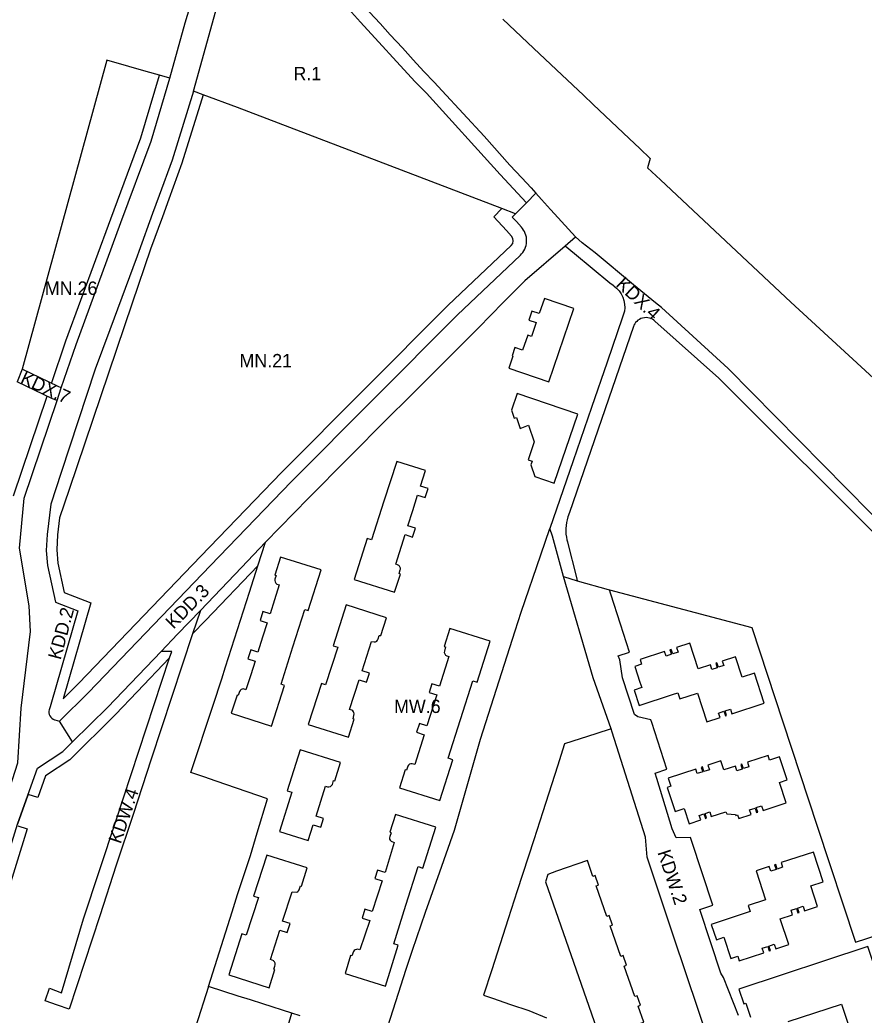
# Model space of a CAD drawing. Extents: x 7416797 to 7419013, y 5549660 to 5551534.
# Drawn here: x 7417362.3 to 7417678.6, y 5550624.8 to 5550997.5 of the extents above; entities that cross this region are included whole.
import ezdxf

# ---------------------------------------------------------------- set-up
doc = ezdxf.new("R2010")
doc.units = 0
for name, color, linetype in [('LIN_Linia Zabudowy Nieprzekraczalna', 7, 'Continuous'), ('LIN_Linia Zabudowy Obowiązujaca', 7, 'Continuous'), ('LIN_linie_rozgraniczajace', 7, 'Continuous'), ('TXT_Oznaczenia_przeznaczen', 7, 'Continuous')]:
    doc.layers.add(name, color=color, linetype=linetype)

msp = doc.modelspace()

# ---------------------------------------------------------------- linework, layer by layer
at = {"layer": 'LIN_Linia Zabudowy Nieprzekraczalna'}
msp.add_line((7417543.12, 5550920.3), (7417544.66, 5550918.61), dxfattribs=at)
for points in [[(7417374.19, 5550861.35), (7417379.59, 5550877.27), (7417396.44, 5550923.04), (7417407.68, 5550953.34), (7417414.63, 5550976.83)], [(7417431.02, 5550969.42), (7417423.05, 5550943.81), (7417418.15, 5550930.44), (7417415.7, 5550923.73), (7417411.27, 5550911.64)], [(7417546.54, 5550916.54), (7417544.66, 5550918.61), (7417539.91, 5550923.81), (7417542.9, 5550926.83)], [(7417377.21, 5550811.01), (7417376.47, 5550804.65), (7417376.12, 5550799.09), (7417376.56, 5550794.09), (7417378.94, 5550783.04), (7417388.87, 5550779.22), (7417378.53, 5550743.27), (7417384.4, 5550749.09), (7417430.11, 5550796.7), (7417460.4, 5550828.04), (7417522.84, 5550890.7), (7417546.41, 5550913.04)], [(7417411.27, 5550911.64), (7417404.39, 5550891.44), (7417380.8, 5550821.69), (7417377.21, 5550811.01)], [(7417359.92, 5550819.22), (7417372.58, 5550856.58)], [(7417451.53, 5550793.03), (7417431.87, 5550772.61), (7417427.03, 5550767.55)], [(7417418.42, 5550758.55), (7417406.27, 5550745.84), (7417398.18, 5550737.38), (7417380.98, 5550720.38), (7417371.85, 5550714.38), (7417369.03, 5550706.25), (7417365.43, 5550707.39), (7417365.35, 5550707.16), (7417361.36, 5550696.33)], [(7417361.58, 5550695.63), (7417365.01, 5550694.6), (7417356.26, 5550666.29)], [(7417399.46, 5550459.54), (7417410.81, 5550455.77), (7417421, 5550486.78), (7417446.8, 5550568.03), (7417455.32, 5550595.79), (7417464.2, 5550625.52)]]:
    msp.add_lwpolyline(points, dxfattribs=at)
msp.add_arc((7417544.69, 5550914.85), 2.5, 313.4663, 42.3592, dxfattribs=at)
at = {"layer": 'LIN_Linia Zabudowy Obowiązujaca'}
for p, q in [((7417509.59, 5550813.78), (7417511.33, 5550819.54)), ((7417464.61, 5550762.7), (7417469.04, 5550776.73)), ((7417460.17, 5550748.69), (7417464.61, 5550762.7)), ((7417476.79, 5550710.49), (7417477.57, 5550710.25))]:
    msp.add_line(p, q, dxfattribs=at)
for points in [[(7417569.85, 5550889.48), (7417558.85, 5550893.19), (7417556.92, 5550887.5), (7417554.13, 5550888.45), (7417553, 5550885.09), (7417555.79, 5550884.16), (7417554.05, 5550879.01), (7417552.61, 5550879.49), (7417550.68, 5550873.83), (7417547.8, 5550874.79), (7417546.72, 5550871.71), (7417547.03, 5550871.61), (7417545.49, 5550867.1), (7417560.47, 5550861.95)], [(7417562.53, 5550824.03), (7417571.34, 5550849.82), (7417548.61, 5550857.59), (7417546.46, 5550851.36), (7417547.52, 5550848.32), (7417548.34, 5550848.61), (7417549.79, 5550844.55), (7417552.91, 5550845.78), (7417555.05, 5550839.52), (7417552.78, 5550832.8), (7417554.2, 5550832.32), (7417553.75, 5550830.86), (7417555.3, 5550826.52)], [(7417603.89, 5550760.97), (7417594.7, 5550757.96), (7417595.27, 5550756.24), (7417592.69, 5550755.39), (7417594.64, 5550749.47), (7417595.3, 5550747.48), (7417592.46, 5550746.53), (7417594.35, 5550740.76), (7417606.87, 5550744.88), (7417608.88, 5550745.54), (7417609.63, 5550743.26), (7417616.19, 5550745.42), (7417619.75, 5550734.6), (7417624.64, 5550736.21), (7417624.08, 5550737.92), (7417626.08, 5550738.58), (7417626.65, 5550736.87), (7417627.11, 5550737.02), (7417626.55, 5550738.73), (7417628.55, 5550739.39), (7417629.12, 5550737.68), (7417641.19, 5550741.64), (7417637.53, 5550752.83), (7417632.97, 5550751.34), (7417630.43, 5550759.02), (7417625.51, 5550757.38), (7417626.07, 5550755.69), (7417624.06, 5550755.05), (7417623.5, 5550756.74), (7417623.04, 5550756.58), (7417623.6, 5550754.91), (7417621.59, 5550754.24), (7417621.02, 5550755.93), (7417616.47, 5550754.44), (7417613.29, 5550764.07), (7417608.39, 5550762.45), (7417608.95, 5550760.73), (7417606.92, 5550760.07), (7417606.35, 5550761.79), (7417605.9, 5550761.63), (7417606.46, 5550759.93), (7417604.46, 5550759.27)], [(7417605.27, 5550713.53), (7417606.27, 5550710.49), (7417604.84, 5550710.03), (7417607.81, 5550701.05), (7417611.22, 5550702.15), (7417613.08, 5550696.45), (7417617.44, 5550697.88), (7417616.89, 5550699.6), (7417618.6, 5550700.16), (7417619.16, 5550698.45), (7417619.63, 5550698.6), (7417619.07, 5550700.32), (7417620.78, 5550700.88), (7417621.35, 5550699.17), (7417626.87, 5550700.97), (7417627.14, 5550700.16), (7417630.47, 5550699.89), (7417630.58, 5550699.59), (7417631.23, 5550699.86), (7417631.69, 5550698.47), (7417636.31, 5550699.98), (7417635.75, 5550701.7), (7417637.78, 5550702.36), (7417638.33, 5550700.65), (7417638.78, 5550700.8), (7417638.22, 5550702.51), (7417640.25, 5550703.17), (7417640.81, 5550701.46), (7417649.45, 5550704.29), (7417646.94, 5550711.97), (7417649.77, 5550712.9), (7417646.94, 5550721.53), (7417643.22, 5550720.32), (7417642.66, 5550722.03), (7417634.9, 5550719.48), (7417635.46, 5550717.77), (7417633.43, 5550717.1), (7417632.87, 5550718.81), (7417632.43, 5550718.67), (7417632.99, 5550716.96), (7417630.96, 5550716.29), (7417630.4, 5550718.01), (7417626.12, 5550716.62), (7417624.99, 5550720.02), (7417620.08, 5550718.41), (7417620.65, 5550716.69), (7417618.61, 5550716.03), (7417618.06, 5550717.74), (7417617.61, 5550717.59), (7417618.17, 5550715.89), (7417616.13, 5550715.23), (7417615.6, 5550716.93)], [(7417563.44, 5550678.69), (7417560.16, 5550677.49), (7417559.27, 5550674.67), (7417578.38, 5550619.91), (7417581.25, 5550617.11), (7417584.57, 5550618.16), (7417596.07, 5550622.21), (7417593.98, 5550628.2), (7417594.83, 5550628.5), (7417593.6, 5550632.03), (7417592.75, 5550631.73), (7417588.77, 5550643.17), (7417589.64, 5550643.47), (7417588.37, 5550647.07), (7417587.51, 5550646.77), (7417583.53, 5550658.19), (7417584.37, 5550658.48), (7417583.15, 5550662.08), (7417582.28, 5550661.78), (7417578.3, 5550673.18), (7417579.15, 5550673.48), (7417577.91, 5550677.07), (7417577.05, 5550676.77), (7417574.97, 5550682.74)], [(7417638.19, 5550678.84), (7417641.7, 5550667.99), (7417635.14, 5550665.84), (7417635.89, 5550663.57), (7417621.36, 5550658.78), (7417623.28, 5550653.01), (7417626.13, 5550653.96), (7417628.72, 5550646.05), (7417631.29, 5550646.91), (7417631.85, 5550645.17), (7417641.02, 5550648.14), (7417640.47, 5550649.86), (7417642.51, 5550650.53), (7417643.07, 5550648.82), (7417643.5, 5550648.95), (7417642.92, 5550650.66), (7417644.96, 5550651.33), (7417645.53, 5550649.63), (7417650.43, 5550651.23), (7417647.19, 5550660.87), (7417651.82, 5550662.37), (7417651.26, 5550664.07), (7417653.28, 5550664.74), (7417653.84, 5550663.05), (7417654.28, 5550663.19), (7417653.71, 5550664.88), (7417655.75, 5550665.56), (7417656.31, 5550663.86), (7417661.23, 5550665.47), (7417658.73, 5550673.17), (7417663.29, 5550674.68), (7417659.64, 5550685.83), (7417647.56, 5550681.92), (7417648.12, 5550680.19), (7417646.09, 5550679.52), (7417645.54, 5550681.23), (7417645.09, 5550681.1), (7417645.67, 5550679.38), (7417643.63, 5550678.71), (7417643.07, 5550680.42)]]:
    msp.add_lwpolyline(points, close=True, dxfattribs=at)
for points in [[(7417511.33, 5550819.54), (7417514.17, 5550818.67), (7417515.24, 5550821.99), (7417512.43, 5550822.91), (7417514.25, 5550828.77), (7417503.51, 5550832.15), (7417498.72, 5550817.23)], [(7417498.72, 5550817.23), (7417494.12, 5550802.75), (7417492.43, 5550803.29), (7417487.55, 5550787.92)], [(7417503.76, 5550793.42), (7417503.13, 5550793.65), (7417506.65, 5550804.75), (7417509.47, 5550803.81), (7417510.51, 5550807.15), (7417507.71, 5550808.03), (7417509.59, 5550813.78)], [(7417459.97, 5550796.34), (7417457.85, 5550789.61), (7417458.32, 5550789.46), (7417457.87, 5550788.03)], [(7417469.04, 5550776.73), (7417470.31, 5550776.33), (7417475.14, 5550791.56), (7417459.97, 5550796.34)], [(7417487.55, 5550787.92), (7417502.7, 5550783.18), (7417504.97, 5550789.96), (7417504.42, 5550790.16), (7417504.86, 5550791.52)], [(7417458.53, 5550786.22), (7417459.48, 5550785.92), (7417457.71, 5550780.31)], [(7417457.71, 5550780.31), (7417456.04, 5550775.08), (7417453.36, 5550775.94), (7417452.29, 5550772.59), (7417454.98, 5550771.73), (7417453.25, 5550766.29)], [(7417496.61, 5550765.71), (7417496.93, 5550767.01), (7417497.56, 5550766.91), (7417499.66, 5550773.64), (7417484.59, 5550778.48), (7417479.65, 5550763.1), (7417481.4, 5550762.54), (7417476.88, 5550748.48), (7417475.28, 5550748.99), (7417470.35, 5550733.64)], [(7417507.62, 5550718), (7417507.12, 5550716.53), (7417506.67, 5550716.71), (7417504.54, 5550709.95), (7417519.69, 5550705.17), (7417524.52, 5550720.44), (7417522.8, 5550721), (7417531.99, 5550750.03), (7417533.7, 5550749.51), (7417538.57, 5550764.8), (7417523.41, 5550769.61)], [(7417523.41, 5550769.61), (7417521.29, 5550762.83), (7417521.78, 5550762.73), (7417521.39, 5550761.16)], [(7417453.25, 5550766.29), (7417451.5, 5550760.79), (7417448.84, 5550761.63), (7417447.77, 5550758.27), (7417450.43, 5550757.42), (7417448.81, 5550752.29)], [(7417486.7, 5550739.02), (7417485.84, 5550739.31), (7417489.41, 5550750.34), (7417492.17, 5550749.44), (7417493.28, 5550752.88), (7417490.53, 5550753.77), (7417494.07, 5550764.72), (7417495.02, 5550764.59)], [(7417522.32, 5550759.36), (7417523.04, 5550759.11), (7417519.53, 5550748.01), (7417516.69, 5550748.91), (7417515.68, 5550745.58), (7417518.48, 5550744.69), (7417514.82, 5550733.15), (7417512.01, 5550734.04), (7417510.95, 5550730.71), (7417513.76, 5550729.82), (7417510.25, 5550718.72), (7417509.36, 5550718.95)], [(7417448.81, 5550752.29), (7417447.01, 5550746.65), (7417446.06, 5550746.96)], [(7417444.66, 5550746.02), (7417444.15, 5550744.46), (7417443.68, 5550744.61), (7417441.48, 5550737.85), (7417456.59, 5550733.06), (7417461.42, 5550748.29), (7417460.17, 5550748.69)], [(7417470.35, 5550733.64), (7417485.43, 5550728.88), (7417487.56, 5550735.63), (7417487.13, 5550735.77), (7417487.62, 5550737.68)], [(7417479.4, 5550711.2), (7417479.85, 5550712.66), (7417480.32, 5550712.52), (7417482.48, 5550719.37), (7417467.31, 5550724.16), (7417462.46, 5550708.8), (7417464.17, 5550708.26), (7417459.55, 5550693.6), (7417470.34, 5550690.2), (7417472.2, 5550696.08), (7417475.03, 5550695.19), (7417476.08, 5550698.49), (7417473.28, 5550699.37), (7417476.79, 5550710.49)], [(7417506.94, 5550665.97), (7417511.53, 5550680.42), (7417513.25, 5550679.89), (7417518.12, 5550695.25), (7417503, 5550699.97), (7417500.9, 5550693.27), (7417501.44, 5550693.01), (7417500.93, 5550691.69)], [(7417501.44, 5550689.96), (7417502.6, 5550689.48), (7417499.16, 5550678.25), (7417496.35, 5550679.14), (7417495.35, 5550675.98), (7417498.06, 5550675.13), (7417496.17, 5550669.37)], [(7417454.83, 5550684.72), (7417449.88, 5550669.38), (7417451.71, 5550668.79), (7417447.16, 5550654.7), (7417445.51, 5550655.23), (7417440.57, 5550639.89), (7417455.7, 5550635.01), (7417457.87, 5550641.83), (7417457.48, 5550642.01), (7417457.83, 5550643.11)], [(7417467.03, 5550672.06), (7417467.4, 5550673.22), (7417467.82, 5550673.09), (7417469.98, 5550679.92), (7417454.83, 5550684.72)], [(7417457.41, 5550645.19), (7417456.17, 5550645.59), (7417459.75, 5550656.62), (7417462.48, 5550655.74), (7417463.58, 5550659.11), (7417460.76, 5550660.02), (7417464.33, 5550671.02), (7417466.03, 5550670.89)], [(7417496.17, 5550669.37), (7417494.37, 5550663.59), (7417491.57, 5550664.47), (7417490.53, 5550661.12), (7417493.44, 5550660.21), (7417489.74, 5550649.23), (7417488.86, 5550649.46)], [(7417487.26, 5550648.59), (7417486.74, 5550647.02), (7417486.18, 5550647.16), (7417484.15, 5550640.37), (7417499.29, 5550635.59), (7417504.08, 5550650.94), (7417502.44, 5550651.45), (7417506.94, 5550665.97)], [(7417691.15, 5550616.91), (7417688.17, 5550625.98), (7417686.45, 5550625.42), (7417684.94, 5550630.03), (7417686.66, 5550630.59), (7417685.07, 5550635.43), (7417680.06, 5550650.45), (7417631.75, 5550634.56), (7417633.56, 5550628.97), (7417634.32, 5550629.22), (7417636.01, 5550624.02)], [(7417650.16, 5550622.44), (7417670.21, 5550628.87), (7417678.18, 5550604.75)]]:
    msp.add_lwpolyline(points, dxfattribs=at)
for centre, radius, start, end in [((7417503.45, 5550791.97), 1.48, 342.2154, 77.9217), ((7417459.83, 5550787.72), 1.98, 170.9362, 229.1316), ((7417495.07, 5550766.21), 1.62, 268.3489, 341.973), ((7417522.76, 5550760.73), 1.44, 162.5682, 252.0796), ((7417445.94, 5550745.63), 1.33, 84.7065, 163.0506), ((7417485.54, 5550737.24), 2.13, 12.0194, 56.925), ((7417509.12, 5550717.31), 1.65, 81.7973, 155.4697), ((7417477.87, 5550711.91), 1.69, 259.8195, 335.0505), ((7417502.16, 5550691.11), 1.36, 154.9063, 237.9445), ((7417465.6, 5550672.27), 1.45, 287.3406, 351.6183), ((7417488.82, 5550647.63), 1.83, 88.7092, 148.3611), ((7417455.95, 5550643.81), 2, 339.4285, 43.4032)]:
    msp.add_arc(centre, radius, start, end, dxfattribs=at)
at = {"layer": 'LIN_linie_rozgraniczajace'}
msp.add_line((7417382.08, 5550727.09), (7417377.12, 5550734.85), dxfattribs=at)
for points in [[(7417442.51, 5551032.13), (7417448.05, 5551050.3), (7417465.82, 5551030.77), (7417476.59, 5551018.6), (7417481.19, 5551013.78), (7417484.97, 5551009.43), (7417488.94, 5551005.29), (7417493.3, 5551000.38), (7417497.31, 5550996.11), (7417501.07, 5550991.91), (7417505.63, 5550987.05), (7417509.63, 5550982.57), (7417513.62, 5550978.21), (7417517.53, 5550974.17), (7417520.48, 5550970.94), (7417536.24, 5550953.94), (7417545.94, 5550943.12), (7417550.34, 5550938.31), (7417553.87, 5550934.61), (7417555.65, 5550932.59)], [(7417552.13, 5550929.03), (7417542.33, 5550939.66), (7417514.66, 5550970.08), (7417510.3, 5550974.5), (7417489.93, 5550996.68), (7417464.06, 5551025.5), (7417455.78, 5551034.42)], [(7417427.4, 5550970.77), (7417441.99, 5551023.55)], [(7417418.46, 5550975.74), (7417424.22, 5550996.46), (7417431.53, 5551020.38)], [(7417543.24, 5550997.82), (7417547.86, 5550993.46), (7417552.49, 5550989.09), (7417557.03, 5550984.8), (7417565.38, 5550976.91), (7417573.44, 5550969.3), (7417577.11, 5550965.84), (7417581.64, 5550961.56), (7417590.59, 5550953.1), (7417594.55, 5550949.37), (7417598.52, 5550945.61), (7417597.49, 5550942.07), (7417602.31, 5550937.57), (7417651.23, 5550891.75), (7417707.04, 5550840.5), (7417711.06, 5550853.74), (7417725.07, 5550851.88), (7417716.34, 5550822.83), (7417798.86, 5550738.94), (7417843.71, 5550696.94), (7417852.22, 5550689.73), (7417871.75, 5550673.2), (7417881.4, 5550665.03)], [(7417418.46, 5550975.74), (7417414.63, 5550976.83), (7417409.66, 5550978.24), (7417403.15, 5550980.09), (7417394.9, 5550982.43), (7417363.18, 5550866.69)], [(7417377.84, 5550859.67), (7417383.36, 5550875.94), (7417400.19, 5550921.65), (7417411.48, 5550952.07), (7417418.46, 5550975.74)], [(7417427.4, 5550970.77), (7417419.38, 5550944.98), (7417414.52, 5550931.71), (7417412.06, 5550925), (7417406.88, 5550910.84), (7417406.23, 5550909.08), (7417396.02, 5550881.5), (7417390.56, 5550866.68), (7417377.79, 5550827.96), (7417373.9, 5550816.15), (7417372.58, 5550804.79), (7417372.2, 5550798.78), (7417372.69, 5550793.17), (7417375.63, 5550779.49), (7417384.01, 5550776.27), (7417373.88, 5550741.08), (7417373.65, 5550740.29), (7417373.32, 5550739.12)], [(7417548.01, 5550924.88), (7417542.9, 5550926.83), (7417443.79, 5550964.66), (7417431.02, 5550969.42), (7417427.4, 5550970.77)], [(7417552.13, 5550929.03), (7417555.65, 5550932.59)], [(7417555.65, 5550932.59), (7417557.71, 5550930.24), (7417561.14, 5550926.57), (7417562.69, 5550924.91), (7417570.5, 5550916.24)], [(7417548.01, 5550924.88), (7417552.13, 5550929.03)], [(7417550.24, 5550919.91), (7417548.35, 5550921.98), (7417546.81, 5550923.66), (7417548.01, 5550924.88)], [(7417549.85, 5550909.41), (7417550.32, 5550909.89), (7417550.75, 5550910.43), (7417551.14, 5550911.02), (7417551.48, 5550911.66), (7417551.76, 5550912.35), (7417551.98, 5550913.07), (7417552.12, 5550913.82), (7417552.19, 5550914.58), (7417552.18, 5550915.35), (7417552.09, 5550916.1), (7417551.93, 5550916.84), (7417551.7, 5550917.54), (7417551.4, 5550918.21), (7417551.06, 5550918.83), (7417550.66, 5550919.39), (7417550.24, 5550919.91)], [(7417566.64, 5550912.93), (7417570.5, 5550916.24)], [(7417762.67, 5550706.9), (7417771.26, 5550717.97), (7417701.45, 5550793.22), (7417689.8, 5550804.07), (7417627.65, 5550867), (7417602.66, 5550889.86), (7417600.51, 5550891.61), (7417592.25, 5550898.35), (7417577.84, 5550910.26), (7417573.02, 5550914.06), (7417570.5, 5550916.24)], [(7417454.38, 5550801.91), (7417470.44, 5550818.36), (7417500.24, 5550848.38), (7417508.04, 5550856.14), (7417519.81, 5550867.86), (7417527.76, 5550875.84), (7417534.18, 5550882.22), (7417543.45, 5550891.72), (7417551.37, 5550899.66), (7417551.57, 5550899.86), (7417566.64, 5550912.93)], [(7417566.64, 5550912.93), (7417570.09, 5550910.07), (7417583.4, 5550899.06), (7417584.57, 5550898.19), (7417584.92, 5550897.94)], [(7417377.12, 5550734.85), (7417387.97, 5550745.58), (7417433.71, 5550793.24), (7417463.97, 5550824.54), (7417526.33, 5550887.12), (7417549.73, 5550909.3), (7417549.85, 5550909.41)], [(7417584.92, 5550897.94), (7417585.91, 5550897.09), (7417586.81, 5550896.09), (7417587.58, 5550894.95), (7417588.2, 5550893.71), (7417588.64, 5550892.4), (7417588.88, 5550891.05), (7417588.95, 5550889.7), (7417588.83, 5550888.4)], [(7417588.83, 5550888.4), (7417588.09, 5550886.23), (7417582.31, 5550869.37), (7417576.49, 5550852.41), (7417569.61, 5550832.33), (7417560.89, 5550807.03)], [(7417600.24, 5550884.74), (7417599.82, 5550885.08), (7417599.35, 5550885.38), (7417598.82, 5550885.63), (7417598.24, 5550885.83), (7417597.62, 5550885.96), (7417596.98, 5550886.01), (7417596.32, 5550885.98), (7417595.66, 5550885.86), (7417595.03, 5550885.65), (7417594.44, 5550885.37), (7417593.9, 5550885.01), (7417593.42, 5550884.6), (7417593.01, 5550884.15), (7417592.67, 5550883.67), (7417592.4, 5550883.18), (7417592.19, 5550882.69)], [(7417688.61, 5550799.01), (7417624.22, 5550863.36), (7417600.24, 5550884.74)], [(7417592.19, 5550882.69), (7417568.23, 5550812.98), (7417567.67, 5550811.36)], [(7417363.18, 5550866.69), (7417361.33, 5550862.03)], [(7417377.84, 5550859.67), (7417376.6, 5550860.19), (7417363.18, 5550866.69)], [(7417376.24, 5550854.92), (7417374.54, 5550855.63), (7417361.33, 5550862.03)], [(7417376.24, 5550854.92), (7417377.84, 5550859.67)], [(7417290.24, 5550537.11), (7417301.06, 5550538.78), (7417301.49, 5550539.72), (7417302.54, 5550542.26), (7417309.74, 5550561.82), (7417316.13, 5550578.54), (7417318.75, 5550585.48), (7417328.05, 5550616.69), (7417336.82, 5550643.32), (7417340.42, 5550654.22), (7417347.23, 5550674.88), (7417349.61, 5550682.1), (7417354.07, 5550695.63), (7417355.27, 5550699.41), (7417356.63, 5550703.69), (7417358.6, 5550709.88), (7417361.6, 5550719.33), (7417362.74, 5550739.8), (7417366.31, 5550768.44), (7417365.73, 5550778.07), (7417362.23, 5550799.69), (7417363.86, 5550818.4), (7417376.24, 5550854.92)], [(7417567.67, 5550811.36), (7417567.36, 5550810.33), (7417567.11, 5550809.27), (7417566.95, 5550808.19), (7417566.86, 5550807.09), (7417566.86, 5550805.99), (7417566.93, 5550804.9), (7417567.08, 5550803.82), (7417567.31, 5550802.76)], [(7417498.33, 5550614.61), (7417507.1, 5550641.98), (7417509.39, 5550649.12), (7417514.34, 5550663.31), (7417519.65, 5550678.48), (7417525.2, 5550694.12), (7417526.2, 5550697.62), (7417529.19, 5550708.08), (7417534.93, 5550728.18), (7417547.88, 5550768.74), (7417550.12, 5550775.76), (7417557.51, 5550797.22), (7417560.89, 5550807.03)], [(7417565.97, 5550789.01), (7417561.83, 5550804.16), (7417560.89, 5550807.03)], [(7417433.01, 5550635.5), (7417441.84, 5550663.47), (7417443.9, 5550670), (7417448.7, 5550684.63), (7417451.27, 5550693.08), (7417455.13, 5550705.75), (7417435.9, 5550712.39), (7417431.24, 5550714.04), (7417426.4, 5550715.66), (7417434.7, 5550740.83), (7417437.94, 5550750.69), (7417439.41, 5550755.25), (7417443.89, 5550769.25), (7417448.39, 5550783.25), (7417451.53, 5550793.03), (7417454.38, 5550801.91)], [(7417429.95, 5550776.38), (7417445.38, 5550792.44), (7417454.38, 5550801.91)], [(7417567.31, 5550802.76), (7417567.51, 5550802), (7417567.54, 5550801.87), (7417570.88, 5550788.74), (7417571.16, 5550787.5)], [(7417565.97, 5550789.01), (7417571.16, 5550787.5)], [(7417584.23, 5550730.83), (7417583.8, 5550732.06), (7417577.16, 5550751.14), (7417565.97, 5550789.01)], [(7417571.16, 5550787.5), (7417582.68, 5550784.16), (7417583.18, 5550784.07)], [(7417631.62, 5550624.71), (7417625.94, 5550638.85), (7417625, 5550640.51), (7417621.23, 5550651.86), (7417617.07, 5550664.41), (7417621.97, 5550665.99), (7417614.02, 5550690.24), (7417613.59, 5550691.32), (7417608.21, 5550691.21), (7417606.7, 5550694.53), (7417603.2, 5550706.02), (7417600.99, 5550713.38), (7417600.32, 5550715.42), (7417604.68, 5550716.92), (7417599.06, 5550734.36), (7417598.67, 5550735.41), (7417593.84, 5550736.48), (7417592.65, 5550737.34), (7417588.12, 5550751.13), (7417587.08, 5550757.8), (7417586.54, 5550759.31), (7417590.71, 5550760.72), (7417587.34, 5550771.17), (7417583.72, 5550782.41), (7417583.18, 5550784.07)], [(7417583.18, 5550784.07), (7417636.6, 5550769.97), (7417648.21, 5550734.66), (7417661.07, 5550695.58), (7417675.38, 5550652.06), (7417683.92, 5550654.87), (7417720.17, 5550670.42), (7417723.95, 5550661.71), (7417742.92, 5550617.93), (7417750.48, 5550600.49), (7417755.45, 5550589.02), (7417763, 5550571.61), (7417770.45, 5550574.8), (7417823.65, 5550597.62), (7417839.38, 5550604.37)], [(7417429.95, 5550776.38), (7417427.03, 5550767.55), (7417411.54, 5550720.66), (7417404.71, 5550699.92), (7417398.42, 5550680.94), (7417392.22, 5550661.97), (7417380.81, 5550627.08), (7417376.36, 5550628.53), (7417371.77, 5550630.13), (7417373.42, 5550634.85), (7417377.86, 5550633.15), (7417386.2, 5550660.89), (7417398.32, 5550697.48), (7417418.42, 5550758.55), (7417419.24, 5550761.02), (7417415.26, 5550761.04)], [(7417415.26, 5550761.04), (7417421.35, 5550767.42), (7417429.95, 5550776.38)], [(7417415.26, 5550761.04), (7417395.26, 5550740.11), (7417382.08, 5550727.09)], [(7417373.32, 5550739.12), (7417373.21, 5550738.59), (7417373.21, 5550738.02), (7417373.32, 5550737.44), (7417373.55, 5550736.88), (7417373.89, 5550736.38), (7417374.31, 5550735.96), (7417374.79, 5550735.65), (7417375.28, 5550735.44)], [(7417375.28, 5550735.44), (7417375.37, 5550735.41), (7417377.12, 5550734.85)], [(7417583.8, 5550732.06), (7417578.1, 5550730.19), (7417566.38, 5550726.34), (7417563.72, 5550718.08), (7417558.21, 5550700.94), (7417554.84, 5550690.47), (7417548.69, 5550671.33), (7417545.33, 5550660.86), (7417539.18, 5550641.72), (7417536, 5550632.24), (7417539.35, 5550631.12), (7417546.17, 5550628.81), (7417553, 5550626.52), (7417559.65, 5550623.75)], [(7417658.47, 5550485.31), (7417660.63, 5550490.24), (7417656.11, 5550504.73), (7417645.04, 5550537.13), (7417637.84, 5550559.52), (7417636.02, 5550568.92), (7417634.8, 5550572.36), (7417607.34, 5550653.96), (7417597.31, 5550683.99), (7417596.78, 5550691.48), (7417584.23, 5550730.83)], [(7417309.69, 5550514.65), (7417306.66, 5550531.4), (7417310.71, 5550543.64), (7417313.36, 5550551.62), (7417322.85, 5550577.13), (7417325.52, 5550585.62), (7417337.95, 5550624.72), (7417339.62, 5550629.56), (7417348.68, 5550656.48), (7417352.46, 5550667.53), (7417361.36, 5550696.33), (7417365.35, 5550707.16), (7417368.91, 5550717.24), (7417378.45, 5550723.51), (7417382.08, 5550727.09)], [(7417433.01, 5550635.5), (7417428.17, 5550620.35), (7417416.78, 5550584.76), (7417415.74, 5550581.53), (7417410.4, 5550564.88), (7417422.07, 5550561.06)], [(7417467.36, 5550624.51), (7417464.2, 5550625.52), (7417453.29, 5550629.02), (7417448.7, 5550630.48), (7417444.08, 5550631.96), (7417433.01, 5550635.5)]]:
    msp.add_lwpolyline(points, dxfattribs=at)

# ---------------------------------------------------------------- texts
at = {"layer": 'TXT_Oznaczenia_przeznaczen'}
for s, p in [('R.1', (7417464.8, 5550974.94)), ('MN.26', (7417371.67, 5550894.55)), ('MN.21', (7417444.59, 5550867.4)), ('MW.6', (7417502.51, 5550737.95))]:
    msp.add_text(s, height=5, dxfattribs=at).set_placement(p)
for s, rotation, p in [('KDX.4', 316.3851, (7417585.37, 5550898.09)), ('KDX.7', 335.0511, (7417362.14, 5550861.71)), ('KDD.3', 45.4775, (7417419.9, 5550769.12)), ('KDD.2', 75, (7417377.58, 5550757.61)), ('KDW.4', 71.1286, (7417400.08, 5550688.68)), ('KDW.2', 288.242, (7417601.15, 5550685.76))]:
    msp.add_text(s, height=5, rotation=rotation, dxfattribs=at).set_placement(p)

doc.saveas('drawing.dxf')
